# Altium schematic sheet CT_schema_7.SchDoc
size 370 x 245 mm
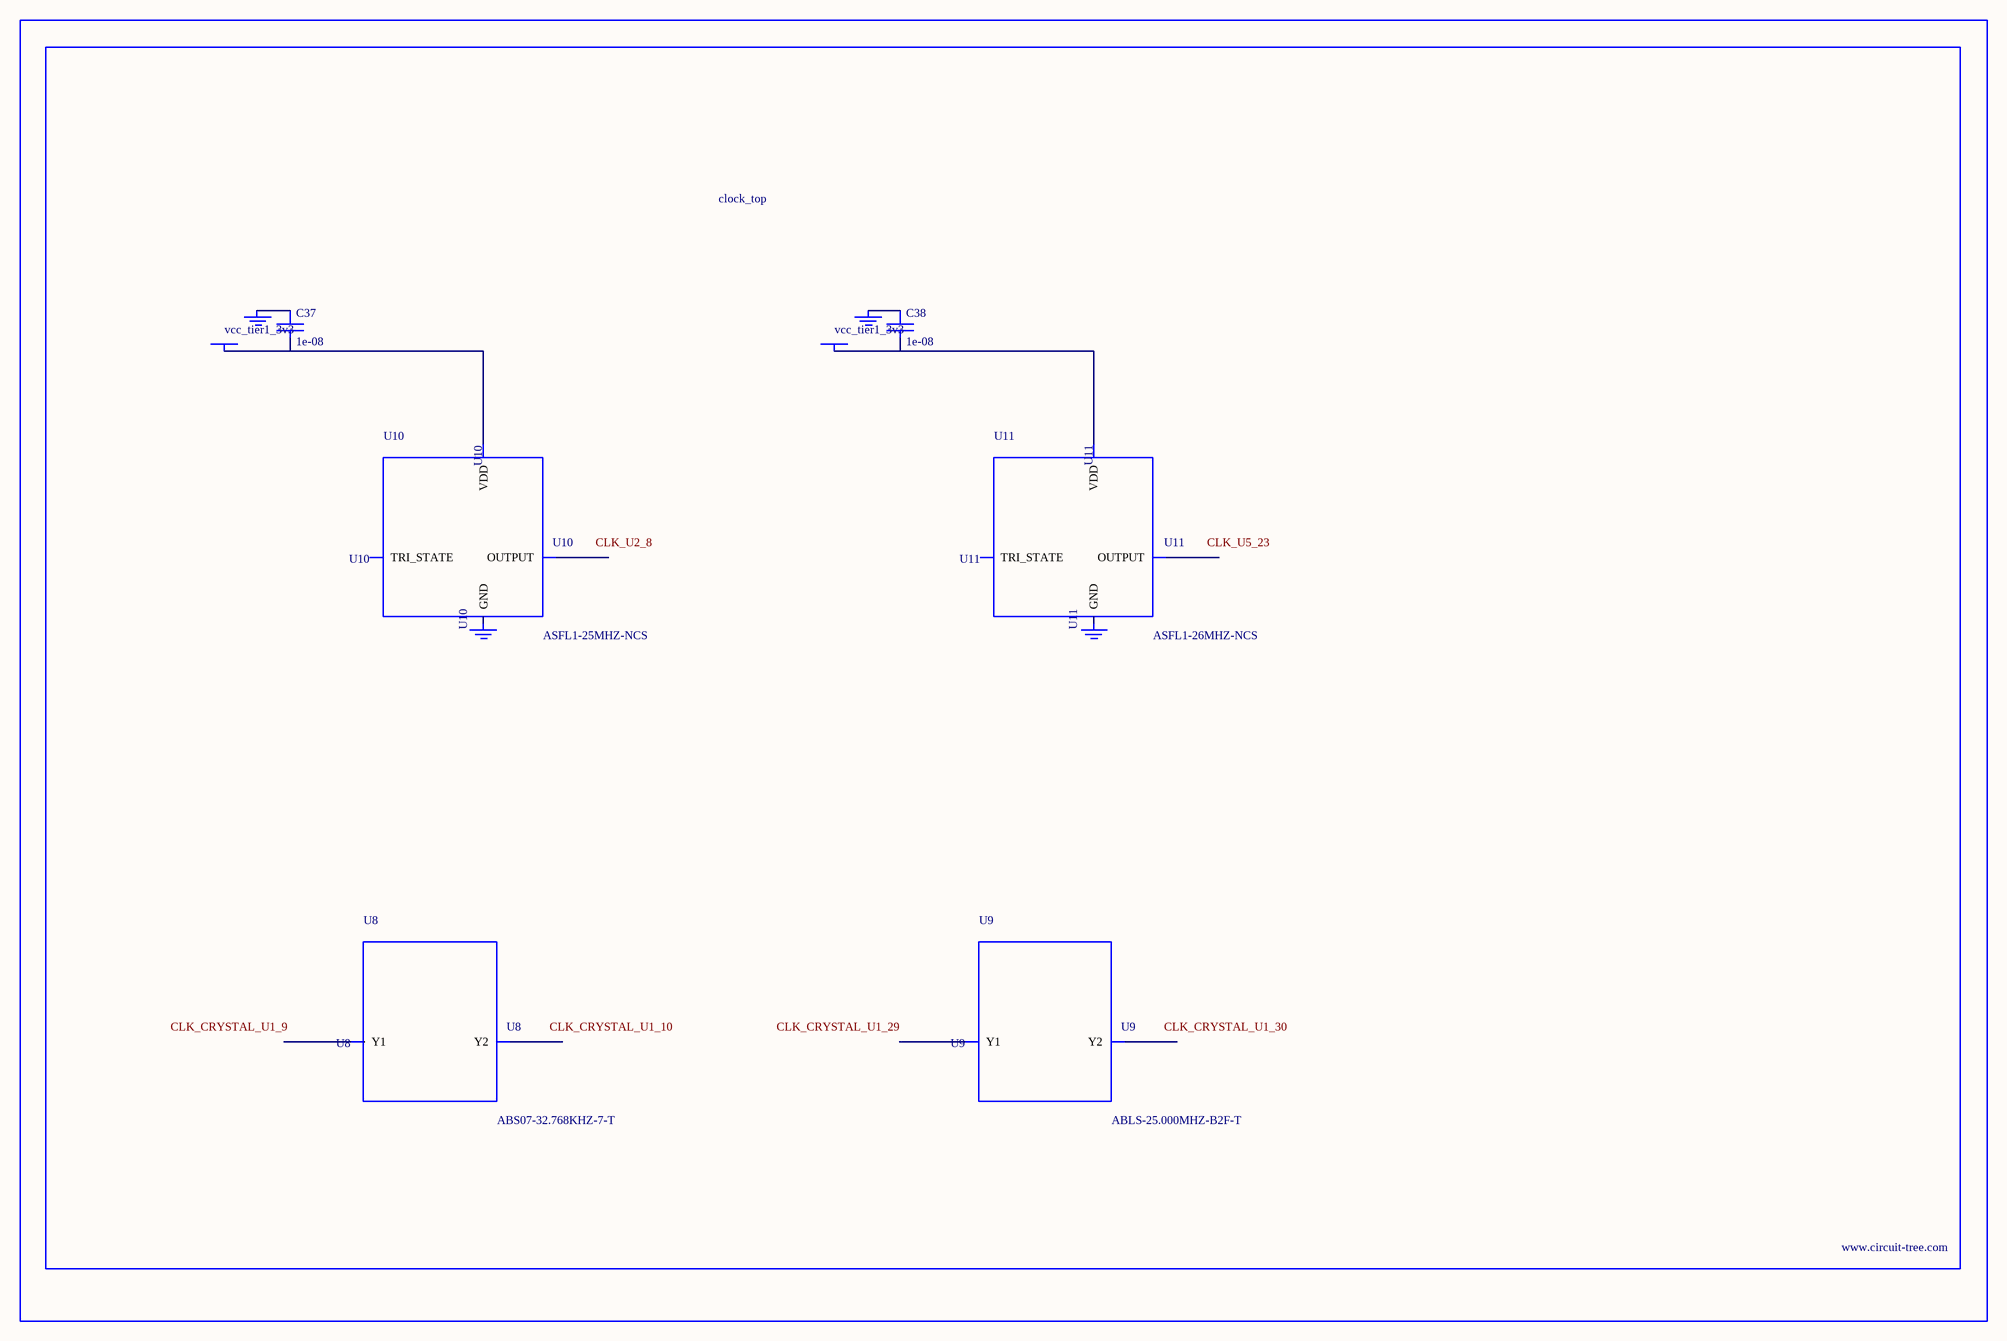
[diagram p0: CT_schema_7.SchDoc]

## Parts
BORDER6  (no value)
C37  1e-08  [C0402]
C38  1e-08  [C0402]
GND_INSTANCE_6_0  (no value)
GND_INSTANCE_6_1  (no value)
GND_INSTANCE_6_2  (no value)
GND_INSTANCE_6_3  (no value)
POWER_INSTANCE_6_0  vcc_tier1_3v3
POWER_INSTANCE_6_1  vcc_tier1_3v3
U8  ABS07-32.768KHZ-7-T  [ABS07-32.768KHZ-7-T]
U9  ABLS-25.000MHZ-B2F-T  [ABLS-25.000MHZ-B2F-T]
U10  ASFL1-25MHZ-NCS  [ASFL1]
U11  ASFL1-26MHZ-NCS  [ASFL1]

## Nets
NetC37_1: C37.1 GND_INSTANCE_6_0.0(GND)
NetC37_2: C37.2 POWER_INSTANCE_6_0.0(PWR) U10.4(VDD)
NetC38_1: C38.1 GND_INSTANCE_6_2.0(GND)
NetC38_2: C38.2 POWER_INSTANCE_6_1.0(PWR) U11.4(VDD)

Not connected (* = marked no-connect by the designer): GND_INSTANCE_6_1 0(GND); GND_INSTANCE_6_3 0(GND); U8 1(Y1) 2(Y2); U9 1(Y1) 2(Y2); U10 1(TRI_STATE) 2(GND) 3(OUTPUT); U11 1(TRI_STATE) 2(GND) 3(OUTPUT)

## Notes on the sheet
- Labels drawn without touching a wire or pin: CLK_CRYSTAL_U1_9, CLK_CRYSTAL_U1_10, CLK_CRYSTAL_U1_29, CLK_CRYSTAL_U1_30, CLK_U2_8, CLK_U5_23

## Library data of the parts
BORDER6 = BORDER_PAGE6
C37 C38 = C0402C103K3RAC
GND_INSTANCE_6_0-GND_INSTANCE_6_3 = GND
POWER_INSTANCE_6_0 POWER_INSTANCE_6_1 = PWR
